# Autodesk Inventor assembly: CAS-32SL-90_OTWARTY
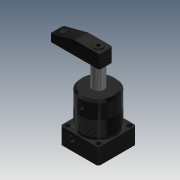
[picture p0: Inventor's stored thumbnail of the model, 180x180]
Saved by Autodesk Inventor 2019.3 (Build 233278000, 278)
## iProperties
Created: 2010-02
Part Number: CAS-32SL-90_OTWARTY
Material: Ogólny
Document SubType Name: Assembly
Designer: CADENGINEERING4
Sending System: PRO/ENGINEER BY PARAMETRIC TECHNOLOGY CORPORATION, 2007170
Preprocessor: PRO/ENGINEER BY PARAMETRIC TECHNOLOGY CORPORATION, 2007170
Title: CAS-32S_ASM
Author: Administrator
Revision Number: 2LAST_VERSION
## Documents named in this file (7)
- D:\Vault_2016\Projekty\STRONA\Pneumatic\Line ; Pipe connecct - type\cas-32s_asm\CAS-32SL-90_OTWARTY.iam
- D:\Vault_2016\Projekty\STRONA\Pneumatic\Line ; Pipe connecct - type\cas-32s_asm\CAS-32BT.ipt
- D:\Vault_2016\Projekty\STRONA\Pneumatic\Line ; Pipe connecct - type\cas-32s_asm\CAS-32SHSG.ipt
- D:\Vault_2016\Projekty\STRONA\Pneumatic\Line ; Pipe connecct - type\cas-32s_asm\CAS-32HG.ipt
- D:\Vault_2016\Projekty\STRONA\Pneumatic\Line ; Pipe connecct - type\cas-32s_asm\CAS-32SYB.ipt
- D:\Vault_2016\Projekty\STRONA\Pneumatic\Line ; Pipe connecct - type\cas-32s_asm\M8LC.ipt
- D:\Vault_2016\Projekty\STRONA\Pneumatic\Line ; Pipe connecct - type\cas-32s_asm\M4.ipt
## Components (9 placed, 9 different names)
1. CAS-32BT_0
2. CAS-32SHSG_1
3. CAS-32HG_2
4. CAS-32SYB_3
5. M8LC_4
6. M4_5
7. M4_6
8. M4_7
9. M4_8
